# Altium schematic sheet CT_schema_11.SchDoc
size 519 x 434 mm
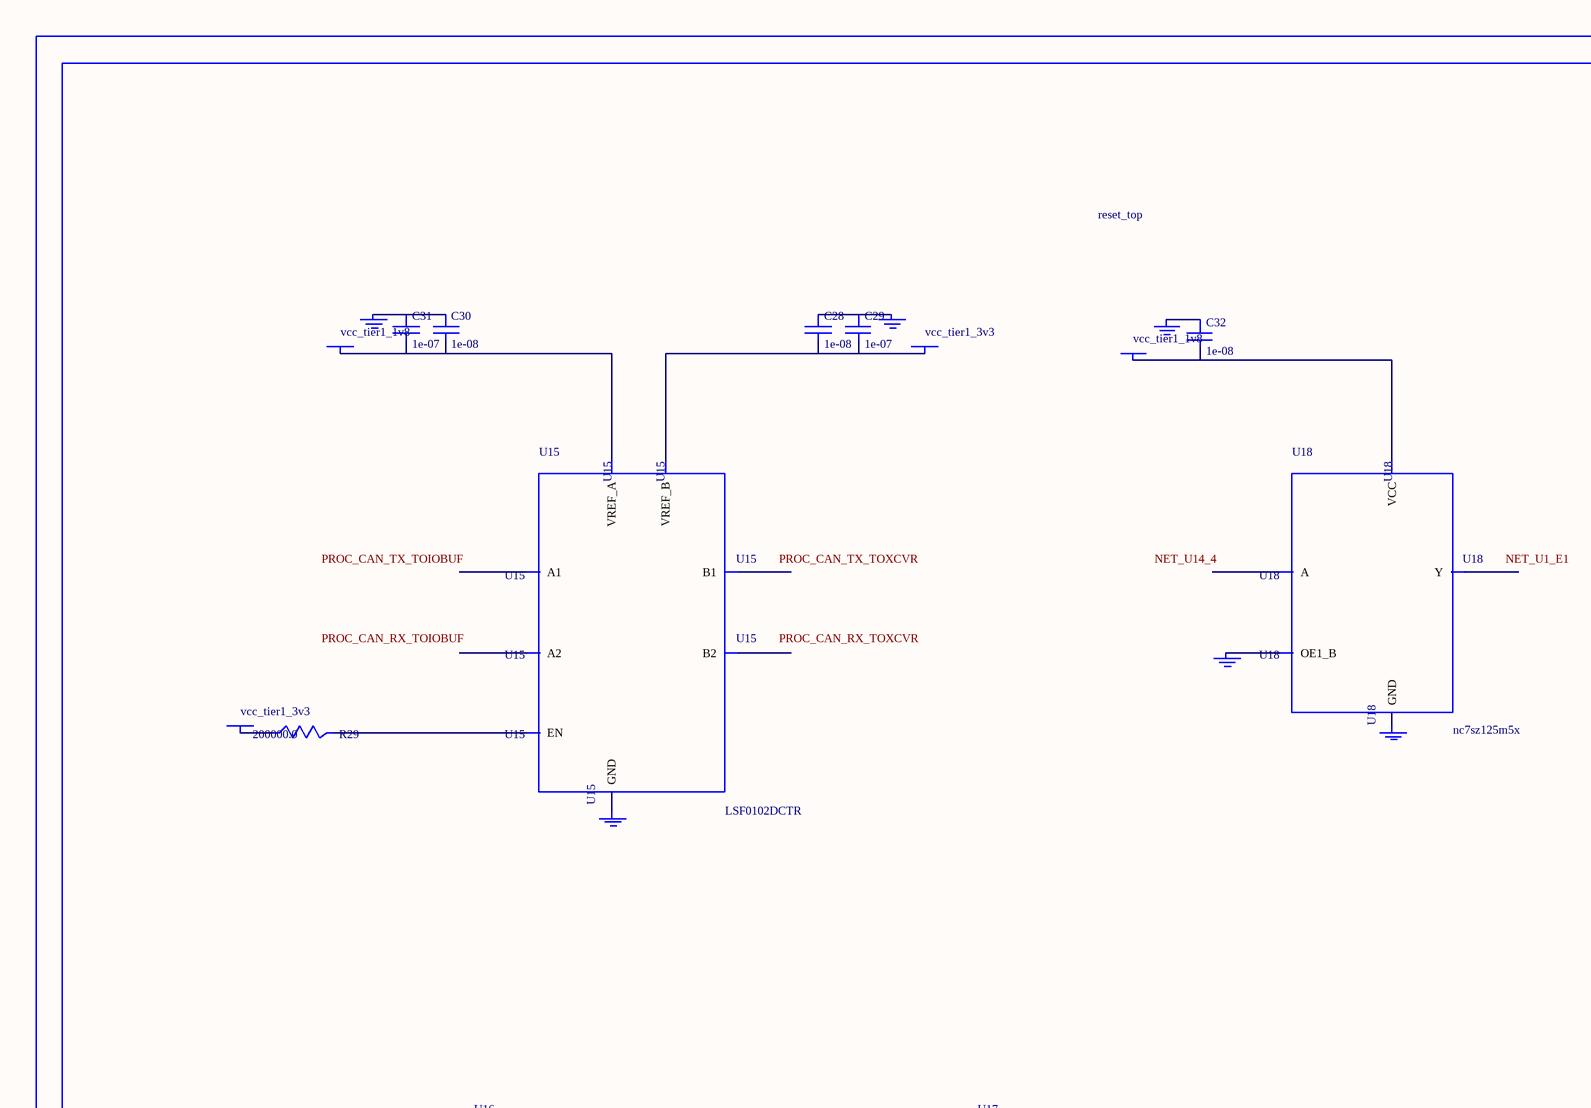
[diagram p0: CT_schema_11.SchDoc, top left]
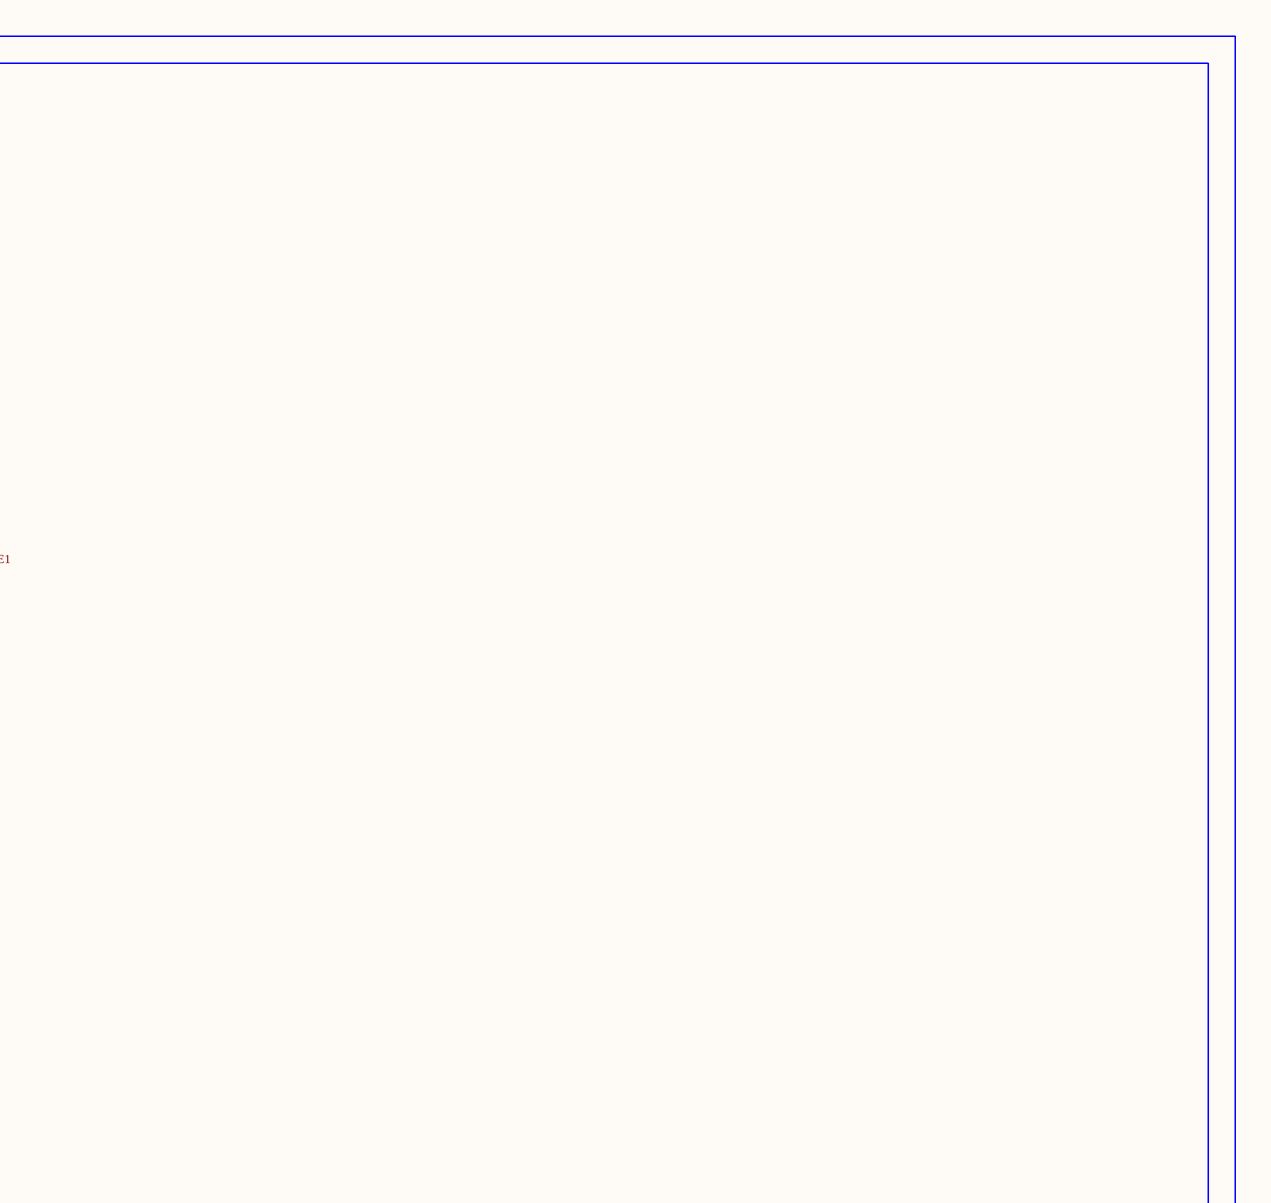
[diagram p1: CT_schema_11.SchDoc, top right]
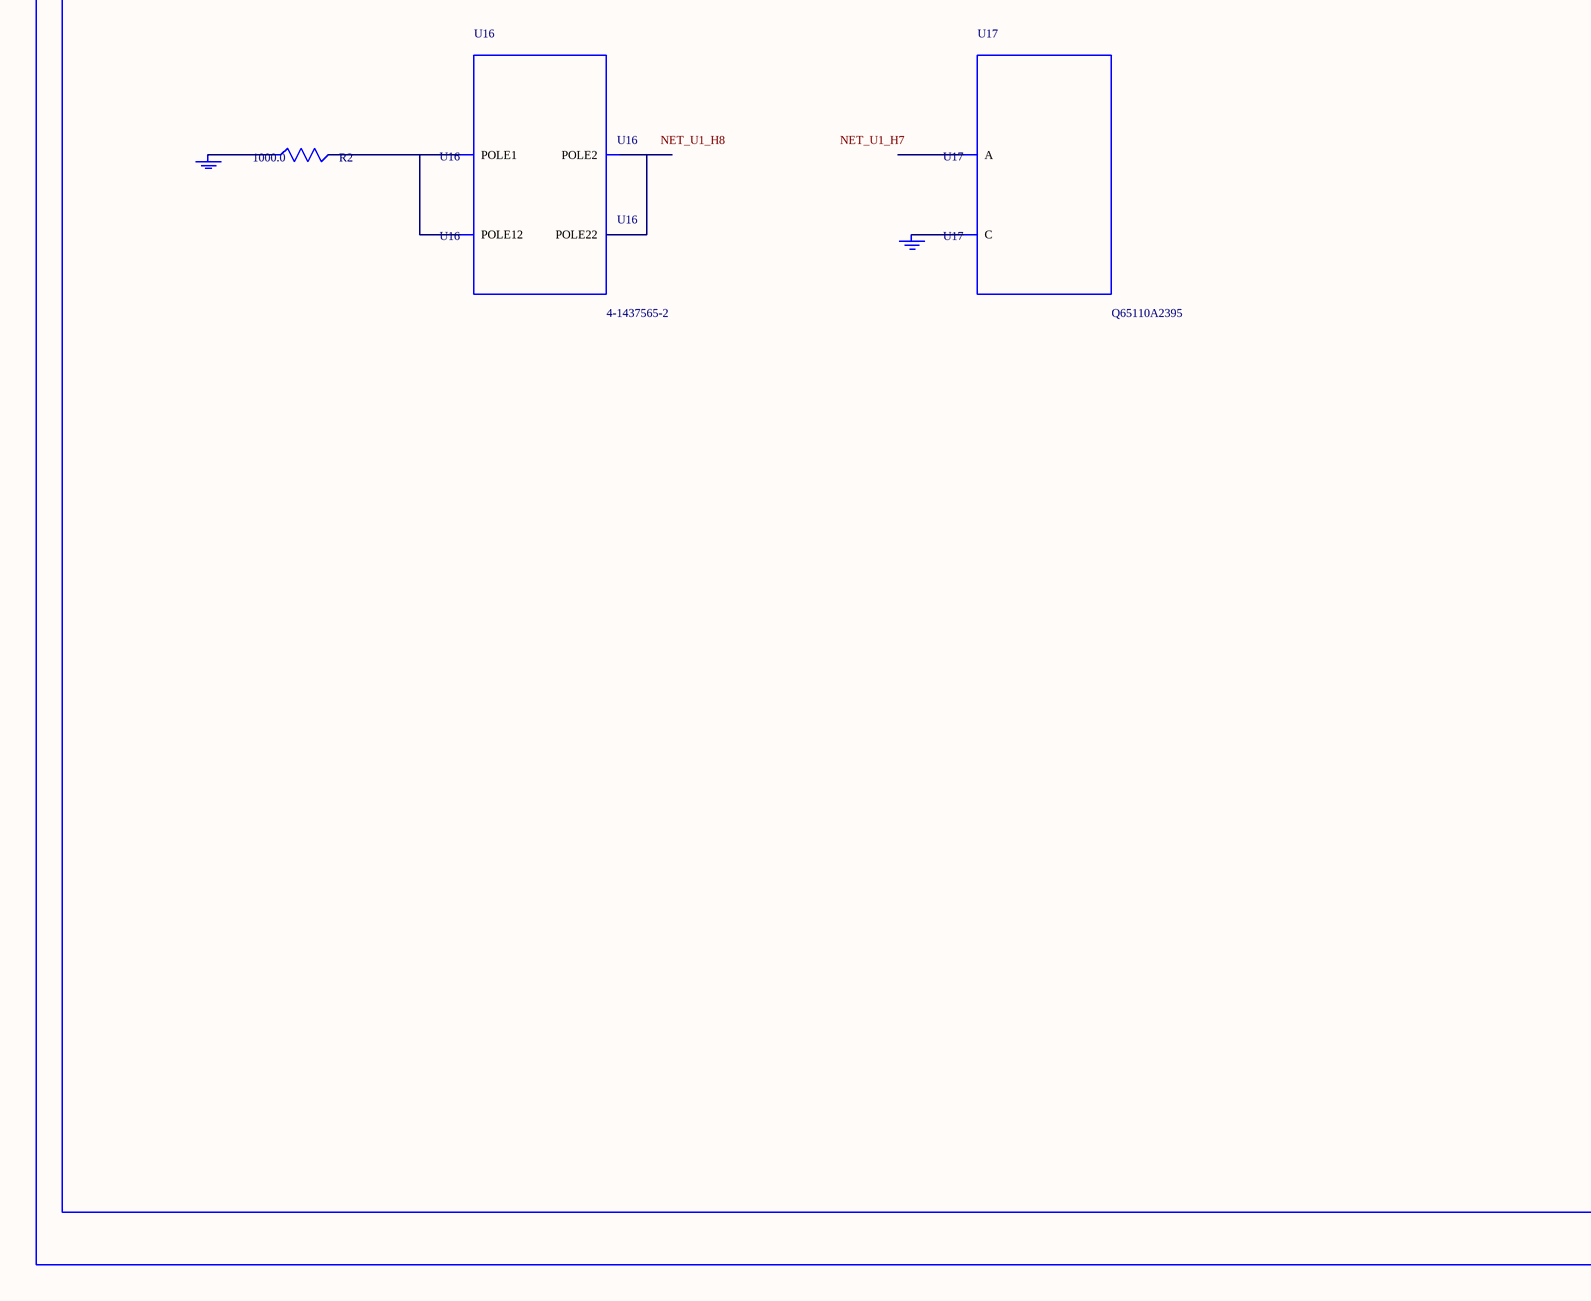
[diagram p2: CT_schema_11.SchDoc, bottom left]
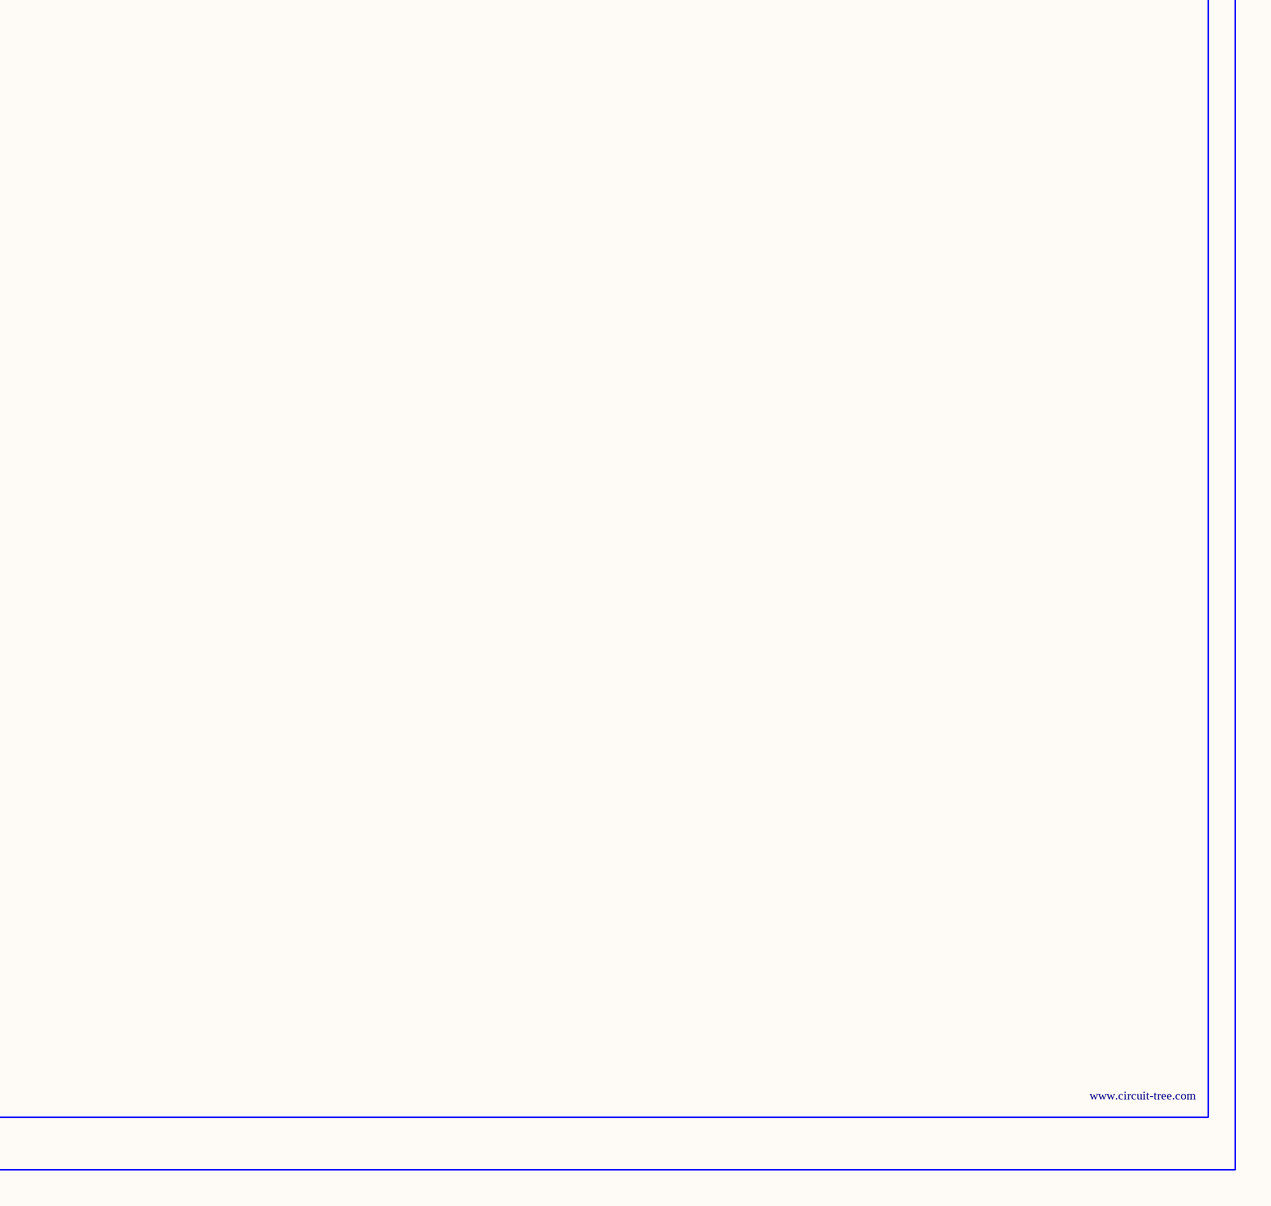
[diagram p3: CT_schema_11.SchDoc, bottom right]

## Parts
BORDER10  (no value)
C28  1e-08  [C0402]
C29  1e-07  [C0402]
C30  1e-08  [C0402]
C31  1e-07  [C0402]
C32  1e-08  [C0402]
GND_INSTANCE_10_0  (no value)
GND_INSTANCE_10_1  (no value)
GND_INSTANCE_10_2  (no value)
GND_INSTANCE_10_3  (no value)
GND_INSTANCE_10_4  (no value)
GND_INSTANCE_10_5  (no value)
GND_INSTANCE_10_6  (no value)
GND_INSTANCE_10_7  (no value)
POWER_INSTANCE_10_0  vcc_tier1_1v8
POWER_INSTANCE_10_1  vcc_tier1_3v3
POWER_INSTANCE_10_2  vcc_tier1_3v3
POWER_INSTANCE_10_3  vcc_tier1_1v8
R2  1000.0  [R0603]
R29  200000.0  [R0603]
U15  LSF0102DCTR  [DCU0008A_N]
U16  4-1437565-2  [SW_4-1437565-2]
U17  Q65110A2395  [LGM67K-G1J2-24-Z]
U18  nc7sz125m5x  [NC7SZ125M5X]

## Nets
NetC28_1: C28.1 C29.1 GND_INSTANCE_10_1.0(GND)
NetC28_2: C28.2 C29.2 POWER_INSTANCE_10_1.0(PWR) U15.7(VREF_B)
NetC30_1: C30.1 C31.1 GND_INSTANCE_10_0.0(GND)
NetC30_2: C30.2 C31.2 POWER_INSTANCE_10_0.0(PWR) U15.2(VREF_A)
NetC32_1: C32.1 GND_INSTANCE_10_5.0(GND)
NetC32_2: C32.2 POWER_INSTANCE_10_3.0(PWR) U18.5(VCC)
NetGND_INSTANCE_10_2_0: GND_INSTANCE_10_2.0(GND) U15.1(GND)
NetGND_INSTANCE_10_3_0: GND_INSTANCE_10_3.0(GND) R2.1
NetGND_INSTANCE_10_4_0: GND_INSTANCE_10_4.0(GND) U17.C
NetGND_INSTANCE_10_6_0: GND_INSTANCE_10_6.0(GND) U18.1(OE1_B)
NetGND_INSTANCE_10_7_0: GND_INSTANCE_10_7.0(GND) U18.3(GND)
NetPOWER_INSTANCE_10_2_0: POWER_INSTANCE_10_2.0(PWR) R29.1
NetR2_2: R2.2 U16.1(POLE1) U16.2(POLE12)
NetR29_2: R29.2 U15.8(EN)
NetU16_3: U16.3(POLE2) U16.4(POLE22)

Not connected (* = marked no-connect by the designer): U15 3(A1) 4(A2) 5(B2) 6(B1); U17 A; U18 2(A) 4(Y)

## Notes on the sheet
- Labels drawn without touching a wire or pin: NET_U1_E1, NET_U1_H7, NET_U1_H8, NET_U14_4, PROC_CAN_RX_TOIOBUF, PROC_CAN_RX_TOXCVR, PROC_CAN_TX_TOIOBUF, PROC_CAN_TX_TOXCVR

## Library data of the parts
BORDER10 = BORDER_PAGE10
C28 C30 C32 = C0402C103K3RAC
C29 C31 = C0402C104K3RACTU
GND_INSTANCE_10_0-GND_INSTANCE_10_7 = GND
POWER_INSTANCE_10_0-POWER_INSTANCE_10_3 = PWR
R2 = RC0603JR-071KL
R29 = RC0603JR-07200KL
